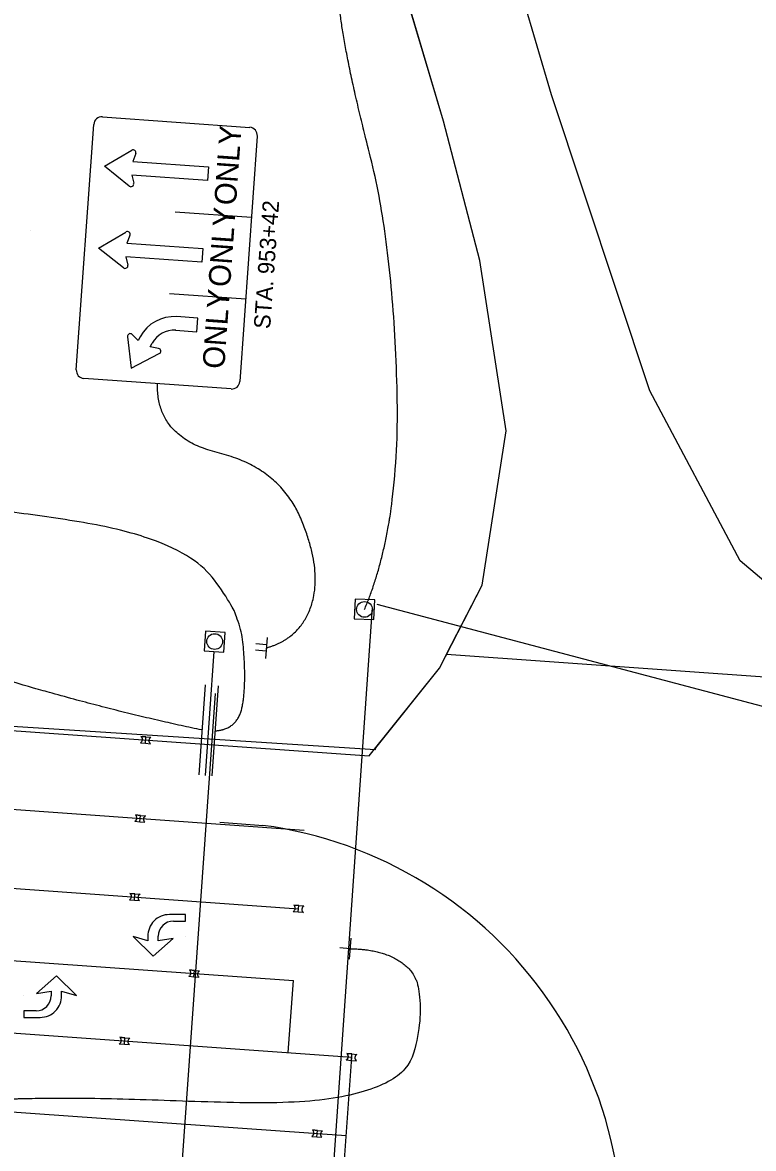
# Model space of a CAD drawing. Extents: x 1847379 to 1850904, y 217032 to 220169.
# Drawn here: x 1849444.7 to 1849556.2, y 218788.3 to 218960 of the extents above; entities that cross this region are included whole.
import ezdxf

# ---------------------------------------------------------------- set-up
doc = ezdxf.new("R2010")
doc.units = 0
for name, color, linetype in [('BR_P_Gen_Approach_Slab_Hidden', 7, 'Continuous'), ('BR_P_Gen_Phase_Construction', 7, 'Continuous'), ('PM_P_Cells', 7, 'Continuous'), ('PM_P_Channelizing_Line', 7, 'Continuous'), ('PM_P_CL_Double_Solid', 7, 'Continuous'), ('PM_P_Dotted_Line', 7, 'Continuous'), ('PM_P_Edge_Line', 7, 'Continuous'), ('PM_P_Lane_Line', 7, 'Continuous'), ('PM_P_Stop_Line', 7, 'Continuous'), ('PM_X_Cells', 7, 'Continuous'), ('PM_X_Dotted_Line', 7, 'Continuous'), ('SG_X_Wiring', 7, 'Continuous'), ('SN_X_Cantilever_Overhead', 7, 'Continuous'), ('SN_X_Foundation', 7, 'Continuous'), ('SN_X_Public', 7, 'Continuous'), ('SN_X_Text', 7, 'Continuous')]:
    doc.layers.add(name, color=color, linetype=linetype)

msp = doc.modelspace()

# ---------------------------------------------------------------- linework, layer by layer
at = {"layer": 'BR_P_Gen_Approach_Slab_Hidden'}
for p, q in [((1849525.36, 218948.96), (1849509.86, 219002.01)), ((1849508.93, 218944.96), (1849493.36, 218997.12)), ((1849540.38, 218903.84), (1849525.36, 218948.96)), ((1849514.45, 218923.71), (1849508.93, 218944.96)), ((1849518.45, 218897.75), (1849514.45, 218923.71)), ((1849554.17, 218877.89), (1849540.38, 218903.84)), ((1849514.81, 218874.18), (1849518.45, 218897.75)), ((1849574.36, 218860.81), (1849554.17, 218877.89)), ((1849509.39, 218863.67), (1849514.81, 218874.18))]:
    msp.add_line(p, q, dxfattribs=at)
msp.add_lwpolyline([(1849366.15, 218857.41), (1849433.63, 218853.3), (1849498.54, 218849.15), (1849498.58, 218849.37), (1849508.29, 218861.54), (1849514.81, 218874.18), (1849518.45, 218897.75), (1849514.45, 218923.71), (1849508.93, 218944.96), (1849493.36, 218997.12), (1849479.33, 219045.76), (1849461.72, 219105.45), (1849446.36, 219158.7), (1849432.03, 219205.83)], dxfattribs=at)
at = {"layer": 'BR_P_Gen_Phase_Construction'}
for p, q in [((1849509.39, 218863.67), (1849582.2, 218858.48)), ((1849474.12, 218857.66), (1849468.24, 218775.2))]:
    msp.add_line(p, q, dxfattribs=at)
at = {"layer": 'PM_P_Cells'}
for p, q in [((1849462.69, 218850.16), (1849463.45, 218850.09)), ((1849462.69, 218850.16), (1849463.45, 218850.09)), ((1849463.54, 218851.06), (1849462.78, 218851.13)), ((1849462.78, 218851.13), (1849463.54, 218851.06)), ((1849463.45, 218850.09), (1849463.54, 218851.06)), ((1849463.45, 218850.09), (1849464.22, 218850.02)), ((1849463.54, 218851.06), (1849464.31, 218850.99)), ((1849461.85, 218838.19), (1849462.62, 218838.12)), ((1849461.85, 218838.19), (1849462.62, 218838.12)), ((1849462.71, 218839.09), (1849461.94, 218839.16)), ((1849461.94, 218839.16), (1849462.71, 218839.09)), ((1849462.62, 218838.12), (1849462.71, 218839.09)), ((1849462.62, 218838.12), (1849463.39, 218838.05)), ((1849462.71, 218839.09), (1849463.47, 218839.02)), ((1849461.87, 218827.12), (1849461.1, 218827.19)), ((1849461.1, 218827.19), (1849461.87, 218827.12)), ((1849461.01, 218826.22), (1849461.78, 218826.15)), ((1849461.01, 218826.22), (1849461.78, 218826.15)), ((1849461.78, 218826.15), (1849461.87, 218827.12)), ((1849461.78, 218826.15), (1849462.55, 218826.08)), ((1849461.87, 218827.12), (1849462.64, 218827.05)), ((1849469.59, 218823.96), (1849467.11, 218823.96)), ((1849469.59, 218822.96), (1849469.59, 218823.96)), ((1849486, 218824.43), (1849486.77, 218824.36)), ((1849486, 218824.43), (1849486.77, 218824.36)), ((1849486.86, 218825.34), (1849486.09, 218825.41)), ((1849486.09, 218825.41), (1849486.86, 218825.34)), ((1849486.77, 218824.36), (1849486.86, 218825.34)), ((1849486.77, 218824.36), (1849487.54, 218824.3)), ((1849486.86, 218825.34), (1849487.63, 218825.27)), ((1849467.73, 218822.96), (1849469.59, 218822.96)), ((1849461.59, 218820.63), (1849461.59, 218820.63)), ((1849463.83, 218819.96), (1849461.59, 218820.63)), ((1849461.59, 218820.63), (1849464.63, 218817.63)), ((1849463.83, 218820.63), (1849463.83, 218819.96)), ((1849465.43, 218819.96), (1849465.43, 218820.66)), ((1849469.59, 218820.63), (1849469.59, 218820.63)), ((1849464.63, 218817.63), (1849467.67, 218820.29)), ((1849467.67, 218820.29), (1849465.43, 218819.96)), ((1849470.95, 218815.45), (1849470.18, 218815.52)), ((1849470.18, 218815.52), (1849470.95, 218815.45)), ((1849470.86, 218814.48), (1849470.95, 218815.45)), ((1849470.95, 218815.45), (1849471.72, 218815.38)), ((1849449.89, 218814.61), (1849446.85, 218811.94)), ((1849452.93, 218811.61), (1849449.89, 218814.61)), ((1849470.09, 218814.55), (1849470.86, 218814.48)), ((1849470.09, 218814.55), (1849470.86, 218814.48)), ((1849470.86, 218814.48), (1849471.63, 218814.41)), ((1849446.85, 218811.94), (1849449.09, 218812.27)), ((1849449.09, 218812.27), (1849449.09, 218811.57)), ((1849450.69, 218811.61), (1849450.69, 218812.27)), ((1849450.69, 218812.27), (1849452.93, 218811.61)), ((1849444.93, 218811.61), (1849444.93, 218811.61)), ((1849452.93, 218811.61), (1849452.93, 218811.61)), ((1849446.79, 218809.27), (1849444.93, 218809.27)), ((1849444.93, 218809.27), (1849444.93, 218808.27)), ((1849444.93, 218808.27), (1849447.41, 218808.27)), ((1849460.33, 218805.17), (1849459.57, 218805.24)), ((1849459.57, 218805.24), (1849460.33, 218805.17)), ((1849460.25, 218804.2), (1849460.33, 218805.17)), ((1849460.33, 218805.17), (1849461.1, 218805.11)), ((1849459.48, 218804.27), (1849460.25, 218804.2)), ((1849459.48, 218804.27), (1849460.25, 218804.2)), ((1849460.25, 218804.2), (1849461.01, 218804.13)), ((1849494.09, 218801.8), (1849494.86, 218801.73)), ((1849494.09, 218801.8), (1849494.86, 218801.73)), ((1849494.95, 218802.7), (1849494.18, 218802.77)), ((1849494.18, 218802.77), (1849494.95, 218802.7)), ((1849494.86, 218801.73), (1849494.95, 218802.7)), ((1849494.86, 218801.73), (1849495.63, 218801.66)), ((1849494.95, 218802.7), (1849495.72, 218802.63)), ((1849488.84, 218790.14), (1849489.61, 218790.08)), ((1849488.84, 218790.14), (1849489.61, 218790.08)), ((1849489.7, 218791.05), (1849488.93, 218791.12)), ((1849488.93, 218791.12), (1849489.7, 218791.05)), ((1849489.61, 218790.08), (1849489.7, 218791.05)), ((1849489.61, 218790.08), (1849490.38, 218790.01)), ((1849489.7, 218791.05), (1849490.47, 218790.98))]:
    msp.add_line(p, q, dxfattribs=at)
for centre, radius, start, end in [((1849462.43, 218850.67), 0.576, 296.8063, 52.8586), ((1849462.43, 218850.67), 0.576, 296.8063, 52.8586), ((1849464.57, 218850.48), 0.576, 116.8063, 232.8586), ((1849461.59, 218838.7), 0.576, 296.8063, 52.8586), ((1849461.59, 218838.7), 0.576, 296.8063, 52.8586), ((1849463.73, 218838.51), 0.576, 116.8063, 232.8586), ((1849460.75, 218826.73), 0.576, 296.8063, 52.8586), ((1849460.75, 218826.73), 0.576, 296.8063, 52.8586), ((1849462.9, 218826.54), 0.576, 116.8063, 232.8586), ((1849467.11, 218820.68), 3.28, 90, 180.9085), ((1849485.74, 218824.95), 0.576, 296.8063, 52.8586), ((1849485.74, 218824.95), 0.576, 296.8063, 52.8586), ((1849487.89, 218824.75), 0.576, 116.8063, 232.8586), ((1849467.73, 218820.66), 2.3, 90, 180), ((1849469.83, 218815.06), 0.576, 296.8063, 52.8586), ((1849469.83, 218815.06), 0.576, 296.8063, 52.8586), ((1849471.98, 218814.87), 0.576, 116.8063, 232.8586), ((1849446.79, 218811.57), 2.3, 270, 360), ((1849447.41, 218811.56), 3.28, 270, 0.9085), ((1849459.22, 218804.78), 0.576, 296.8063, 52.8586), ((1849459.22, 218804.78), 0.576, 296.8063, 52.8586), ((1849461.36, 218804.59), 0.576, 116.8063, 232.8586), ((1849493.83, 218802.31), 0.576, 296.8063, 52.8586), ((1849493.83, 218802.31), 0.576, 296.8063, 52.8586), ((1849495.98, 218802.12), 0.576, 116.8063, 232.8586), ((1849488.58, 218790.66), 0.576, 296.8063, 52.8586), ((1849488.58, 218790.66), 0.576, 296.8063, 52.8586), ((1849490.73, 218790.46), 0.576, 116.8063, 232.8586)]:
    msp.add_arc(centre, radius, start, end, dxfattribs=at)
at = {"layer": 'PM_P_Channelizing_Line'}
for p, q in [((1848983.04, 218860.81), (1849486.82, 218824.85)), ((1848991.59, 218838.14), (1849494.91, 218802.22))]:
    msp.add_line(p, q, dxfattribs=at)
at = {"layer": 'PM_P_CL_Double_Solid'}
msp.add_line((1848992.25, 218849.12), (1849486.03, 218813.88), dxfattribs=at)
at = {"layer": 'PM_P_Dotted_Line'}
msp.add_arc((1849472.91, 218774.84), 63.29, 346.672, 82.3018, dxfattribs=at)
at = {"layer": 'PM_P_Edge_Line'}
for p, q in [((1848960.09, 218886.51), (1849497.6, 218848.14)), ((1849508.29, 218861.54), (1849509.39, 218863.67)), ((1849497.6, 218848.14), (1849508.29, 218861.54))]:
    msp.add_line(p, q, dxfattribs=at)
at = {"layer": 'PM_P_Lane_Line'}
for p, q in [((1848983.9, 218872.78), (1849487.67, 218836.82)), ((1848990.62, 218826.18), (1849494.05, 218790.25))]:
    msp.add_line(p, q, dxfattribs=at)
at = {"layer": 'PM_P_Stop_Line'}
for p, q in [((1849485.25, 218802.91), (1849486.03, 218813.88)), ((1849494.9, 218802.22), (1849493.15, 218778.28))]:
    msp.add_line(p, q, dxfattribs=at)
at = {"layer": 'PM_X_Cells'}
for p, q in [((1849449.89, 218814.61), (1849446.85, 218811.94)), ((1849452.93, 218811.61), (1849449.89, 218814.61)), ((1849446.85, 218811.94), (1849449.09, 218812.27)), ((1849449.09, 218812.27), (1849449.09, 218811.57)), ((1849450.69, 218811.61), (1849450.69, 218812.27)), ((1849450.69, 218812.27), (1849452.93, 218811.61)), ((1849444.93, 218811.61), (1849444.93, 218811.61)), ((1849452.93, 218811.61), (1849452.93, 218811.61)), ((1849446.79, 218809.27), (1849444.93, 218809.27)), ((1849444.93, 218809.27), (1849444.93, 218808.27)), ((1849444.93, 218808.27), (1849447.41, 218808.27))]:
    msp.add_line(p, q, dxfattribs=at)
for centre, radius, end in [((1849446.79, 218811.57), 2.3, 0), ((1849447.41, 218811.56), 3.28, 0.9085)]:
    msp.add_arc(centre, radius, 270, end, dxfattribs=at)
at = {"layer": 'PM_X_Dotted_Line'}
msp.add_line((1849474.8, 218838.03), (1849481.39, 218837.56), dxfattribs=at)
at = {"layer": 'SG_X_Wiring'}
for p, q in [((1849490.27, 218758.57), (1849498.1, 218870.79)), ((1849498.77, 218871.29), (1849599.9, 218844.52))]:
    msp.add_line(p, q, dxfattribs=at)
at = {"layer": 'SN_X_Cantilever_Overhead'}
msp.add_line((1849473.91, 218864.09), (1849472.59, 218845.18), dxfattribs=at)
msp.add_lwpolyline([(1849472.63, 218867.19), (1849472.42, 218864.2), (1849475.41, 218863.99), (1849475.62, 218866.98)], close=True, dxfattribs=at)
msp.add_circle((1849474.02, 218865.59), 1.2, dxfattribs=at)
at = {"layer": 'SN_X_Foundation'}
msp.add_lwpolyline([(1849498.31, 218868.94), (1849498.42, 218871.94), (1849495.42, 218872.04), (1849495.31, 218869.05)], close=True, dxfattribs=at)
msp.add_lwpolyline([(1849498.31, 218868.94), (1849498.42, 218871.94), (1849495.42, 218872.04), (1849495.31, 218869.05)], close=True, dxfattribs=at)
msp.add_circle((1849496.87, 218870.49), 1.2, dxfattribs=at)
msp.add_circle((1849496.87, 218870.49), 1.2, dxfattribs=at)
at = {"layer": 'SN_X_Public'}
for p, q in [((1849457.22, 218938.06), (1849461.39, 218940.51)), ((1849461.99, 218940), (1849461.52, 218938.8)), ((1849461.52, 218938.8), (1849473.09, 218937.98)), ((1849461, 218935.05), (1849457.22, 218938.06)), ((1849473.09, 218937.98), (1849472.94, 218935.9)), ((1849472.94, 218935.9), (1849461.37, 218936.72)), ((1849461.37, 218936.72), (1849461.67, 218935.47)), ((1849468.01, 218931.13), (1849479.64, 218930.3)), ((1849445.98, 218928.33), (1849445.98, 218928.33)), ((1849456.33, 218925.6), (1849460.5, 218928.04)), ((1849461.1, 218927.53), (1849460.63, 218926.33)), ((1849460.11, 218922.58), (1849456.33, 218925.6)), ((1849460.63, 218926.33), (1849472.2, 218925.51)), ((1849472.2, 218925.51), (1849472.05, 218923.43)), ((1849472.05, 218923.43), (1849460.48, 218924.26)), ((1849460.48, 218924.26), (1849460.78, 218923)), ((1849467.12, 218918.67), (1849478.75, 218917.84)), ((1849471.44, 218914.91), (1849468.22, 218915.14)), ((1849471.3, 218912.83), (1849471.44, 218914.91)), ((1849468.07, 218913.06), (1849471.3, 218912.83)), ((1849460.75, 218912.08), (1849461.29, 218907.28)), ((1849462.36, 218911.51), (1849461.46, 218912.42)), ((1849462.66, 218912.07), (1849462.36, 218911.51)), ((1849464.2, 218910.53), (1849464.5, 218911.09)), ((1849465.47, 218910.29), (1849464.2, 218910.53)), ((1849461.29, 218907.28), (1849465.58, 218909.51)), ((1849481.92, 218865.09), (1849480.32, 218865.22)), ((1849482.01, 218866.21), (1849481.75, 218863.02)), ((1849481.84, 218864.14), (1849480.25, 218864.27)), ((1849481.88, 218864.62), (1849481.88, 218864.62)), ((1849472.55, 218858.97), (1849471.59, 218845.25)), ((1849474.55, 218858.83), (1849473.59, 218845.11)), ((1849494.79, 218820.35), (1849494.55, 218817.16)), ((1849494.67, 218818.75), (1849493.08, 218818.87))]:
    msp.add_line(p, q, dxfattribs=at)
for points in [[(1849452.92, 218907.04), (1849455.59, 218944.45)], [(1849456.92, 218945.6), (1849479.37, 218944)], [(1849480.52, 218942.67), (1849477.86, 218905.26)], [(1849476.52, 218904.11), (1849454.08, 218905.71)]]:
    msp.add_lwpolyline(points, dxfattribs=at)
for centre, radius, start, end in [((1849456.83, 218944.36), 1.25, 85.9213, 175.9213), ((1849479.28, 218942.76), 1.25, 355.9213, 85.9213), ((1849461.6, 218940.15), 0.417, 338.5595, 120.4376), ((1849461.26, 218935.37), 0.417, 231.4051, 13.2832), ((1849460.71, 218927.69), 0.417, 338.5595, 120.4376), ((1849460.37, 218922.91), 0.417, 231.4051, 13.2832), ((1849467.81, 218909.32), 5.83, 85.9213, 152.0112), ((1849467.81, 218909.32), 3.75, 85.9213, 152.0227), ((1849461.16, 218912.13), 0.417, 44.6029, 186.481), ((1849465.39, 218909.88), 0.417, 297.4485, 79.3266), ((1849454.17, 218906.95), 1.25, 175.9213, 265.9213), ((1849476.61, 218905.35), 1.25, 265.9213, 355.9213)]:
    msp.add_arc(centre, radius, start, end, dxfattribs=at)
for points in [[(1849496.87, 218870.49), (1849502.46, 218883.6), (1849501.17, 218926.43), (1849493.99, 218954.23), (1849492.19, 218969.57), (1849481.2, 218971.07)], [(1849481.88, 218864.62), (1849487.25, 218866.13), (1849490.44, 218876.61), (1849483.87, 218892.1), (1849465.11, 218896.7), (1849465.3, 218904.91)], [(1849472.07, 218852.11), (1849451.23, 218856.4), (1849396.9, 218874.53), (1849389.39, 218886.8), (1849389.69, 218900.43)], [(1849474.07, 218851.97), (1849477.47, 218852.18), (1849478.91, 218858.87), (1849477.85, 218871.18), (1849466.81, 218882.25), (1849428.48, 218887.21), (1849422.66, 218888.6), (1849423.45, 218898.02)]]:
    msp.add_open_spline(points, degree=2, dxfattribs=at)
at = {"layer": 'SN_X_Text'}
msp.add_open_spline([(1849494.67, 218818.75), (1849500.66, 218818.68), (1849506.53, 218812.81), (1849502.68, 218794.1), (1849444.39, 218796.58), (1849429.74, 218793.85), (1849428.09, 218773.83)], degree=2, dxfattribs=at)

# ---------------------------------------------------------------- texts
at = {"layer": 'SN_X_Public'}
for s, height, p in [('ONLY', 3.333, (1849477.26, 218932.04)), ('STA. 953+42', 2.5, (1849482.47, 218913.2)), ('ONLY', 3.333, (1849476.37, 218919.57)), ('ONLY', 3.333, (1849475.48, 218907.1))]:
    msp.add_text(s, height=height, rotation=85.9213, dxfattribs=at).set_placement(p)

doc.saveas('drawing.dxf')
